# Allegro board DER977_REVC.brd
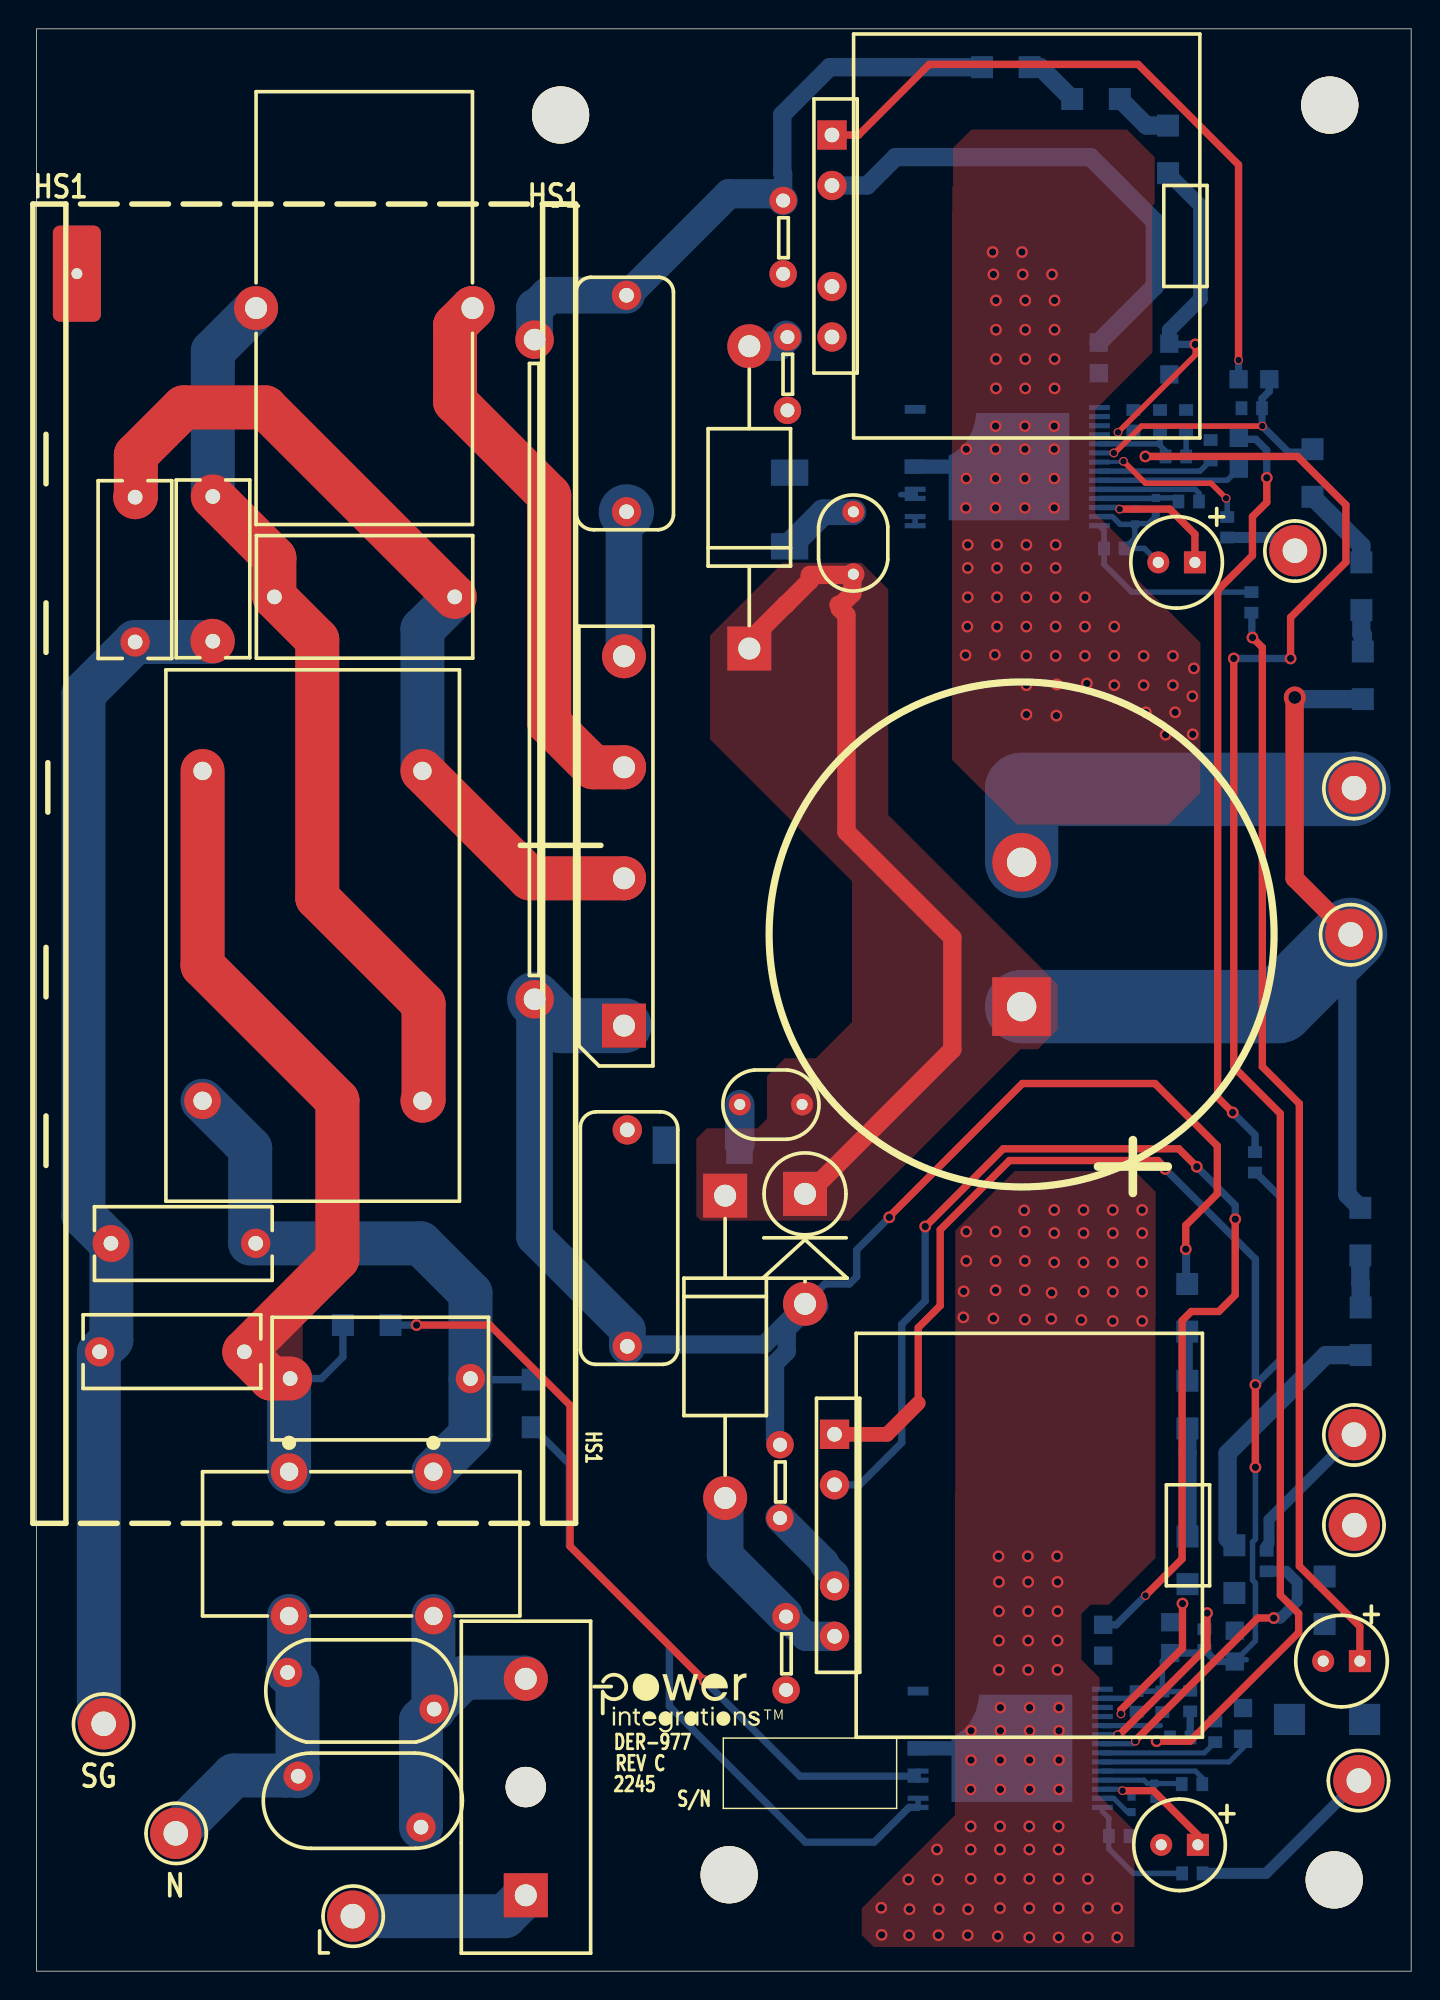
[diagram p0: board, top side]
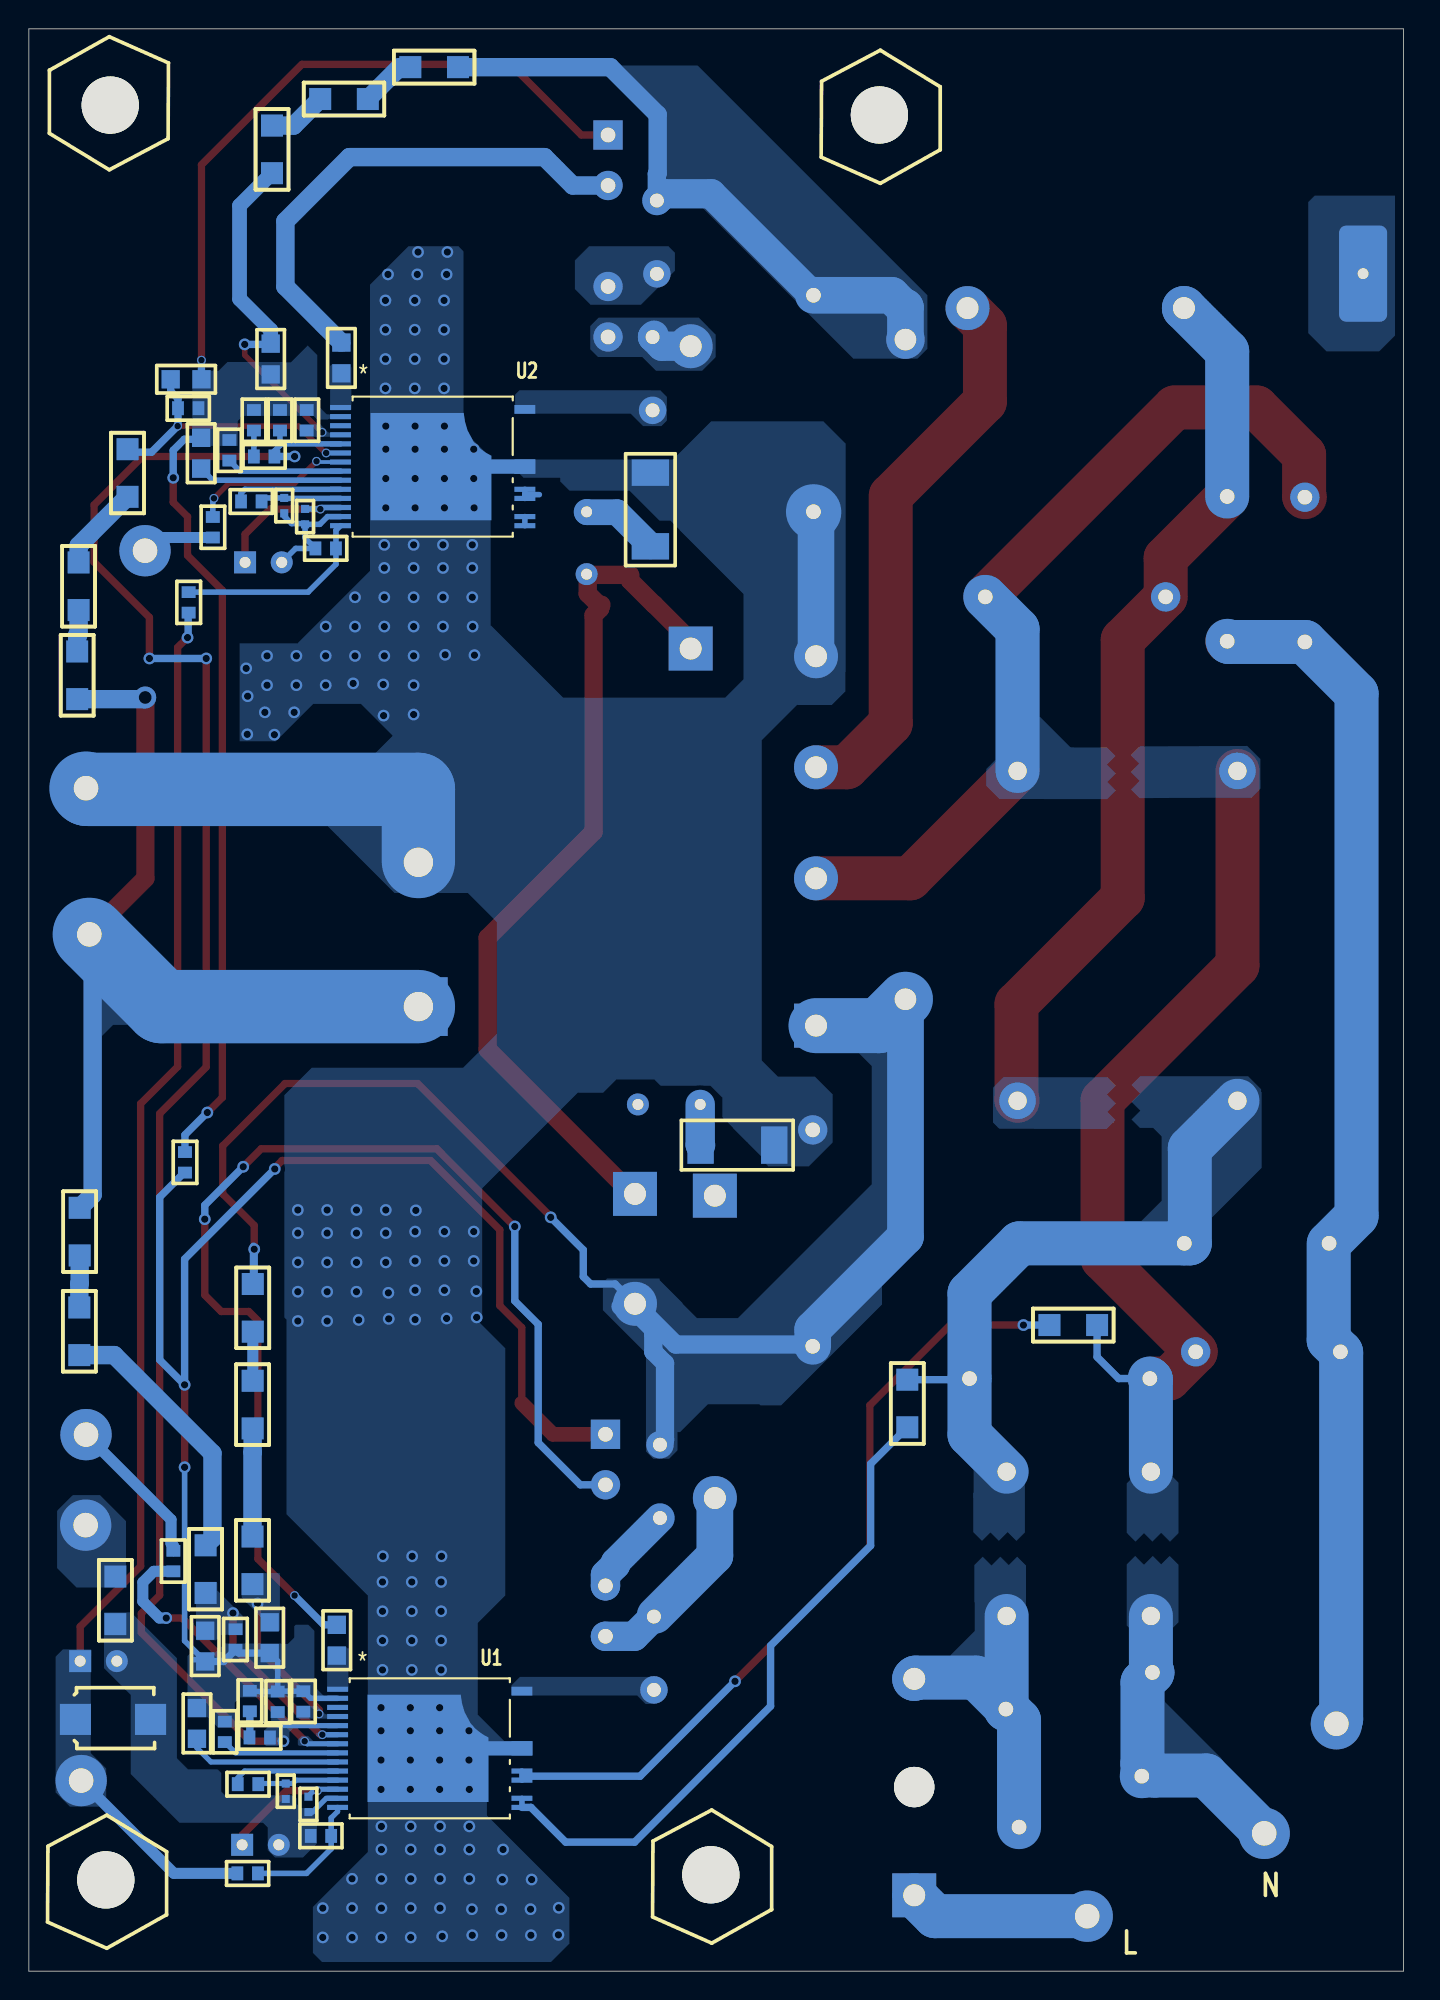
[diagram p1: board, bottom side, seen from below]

Outline 95.28 x 134.62 mm; copper layers: TOP, BOTTOM. Coordinates in mm from the lower left corner of the outline.
Outline path: 0,134.62 95.28,134.62 95.28,0 0,0 0,134.62

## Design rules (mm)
constraint set DEFAULT: min track width 0.508

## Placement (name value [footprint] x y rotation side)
BR1  GBJ1006-BP  [PI_DAX_BRIDG_GBJ]  40.72 65.53 90 top
C1  1 nF  [PI_NP475X200LS395D040]  14.4 42.93 180 top
C2  1 nF  [PI_NP475X200LS395D040]  5.16 50.44 0 top
C3  330 nF  [PINP_XCAPRAD15X8P5X14HD040]  17.58 41.07 0 top
C4  330 nF  [PINP_XCAPRAD15X8P5X14HD040]  16.48 95.25 0 top
C5  1 nF  [PI_NP475X200LS395D040]  6.83 102.16 270 top
C6  1 nF  [PI_NP475X200LS395D040]  12.22 92.18 90 top
C7  680 nF  [PINPCAPRAD17P5X6P7LS15]  40.89 116.15 270 top
C9  47 uF  [PIPOLCAPCYLD250LS100030]  91.72 21.49 180 top
C10  470 pF  [PISMC0603]  76.25 17.98 90 bottom
C11  1 uF  [PISMC0603]  74.32 9.37 0 bottom
C12  100 uF-NP  [PIPOLCAPCYLD250LS100030]  80.49 8.76 180 top
C13  2.2 uF  [PISMC0402]  75.9 12.09 270 bottom
C14  2.2 uF  [PISMC0402]  77.47 13 270 bottom
C15  100 nF  [PISMC0603]  78.03 17.96 90 bottom
C16  1 uF  [PISMC0603]  79.96 18.01 90 bottom
C17  470 pF  [PISMC0603]  80.95 23.7 270 bottom
C18  10 nF  [PI_NP_CAP250X200LS170D030]  53.06 60.07 180 top
C20  10 nF  [PI_NP_CAP250X200LS170D030]  56.62 96.82 90 top
C22  470 pF  [PISMC0603]  76.02 106.78 90 bottom
C23  1 uF  [PISMC0603]  73.99 98.61 0 bottom
C25  2.2 uF  [PISMC0402]  76.13 101.35 270 bottom
C26  100 uF  [PIPOLCAPCYLD250LS100030]  80.29 97.64 180 top
C27  2.2 uF  [PISMC0402]  77.58 102.11 270 bottom
C28  470 pF  [PISMC0603]  84.94 108.33 180 bottom
C29  100 nF  [PISMC0603]  77.87 106.78 90 bottom
C30  1 uF  [PISMC0603]  79.67 106.78 90 bottom
C31  680 nF  [PINPCAPRAD17P5X6P7LS15]  40.94 43.31 90 top
C32  470 uF  [PIPOLCAPCLYD35MMLS10]  68.28 66.85 90 top
C33  2.2 nF  [PINPYCAPRAD540X290LS400040]  17.4 20.7 0 top
D1  S1AB-13-F  [PISMSMB]  92.05 17.45 180 bottom
D2  1N5408G  [PIDV300X200X060DO15D0201AD]  53.26 53.87 270 top
D3  MUR460  [PIDV300X200X060DO15D0201AD#2]  47.73 53.75 270 top
D4  MUR460  [PIDV300X200X060DO15D0201AD#2]  49.4 91.67 90 top
FH1  Fuse Holder  [PI_FUSEHOLDER_5X20MM]  33.91 5.26 0 top
HS1  BRIDGE HEATSINK, SHTM, DER-977,  PI CUST, AL 3003  [PI_HS_1P_DER977]  2.03 31.04 0 top
JP1  J  [PI_JUMPER200]  51.53 36.49 270 top
JP2  J  [PI_JUMPER200]  51.95 24.57 270 top
JP3  J  [PI_JUMPER200]  51.75 122.72 270 top
JP4  J  [PI_JUMPER200]  52.04 113.26 270 top
JP5  J  [PI_JUMPER1800-18AWG-SLD]  34.52 67.36 90 top
L1  1.1 mH  [PIIND4P22X10LS10MM050]  22.5 29.62 270 top
L3  220 uH  [PI2P30X15X15LSD60]  15.21 115.27 0 top
L4  5 mH  [PIIND4P1450X800LS900X600050]  26.75 60.33 180 top
NOREF  -  []  2.41 119.53 0 top
NOREF#2  -  []  -147.56 133.08 0 top
NOREF#3  -  []  0 134.62 0 top
NOREF#4  -  []  95.28 0 90 top
NOREF#5  -  []  -232.28 -146.71 0 top
NOREF#6  -  []  38.53 21.11 0 top
NOREF#7  -  []  2.79 115.77 90 top
POST-CRKT_BRD_6-32_HEX1  Post Hex, 6-32, snap, 0.375L, NYL  [PIMTGHOLED156]  36.32 128.65 270 bottom
POST-CRKT_BRD_6-32_HEX2  Post Hex, 6-32, snap, 0.375L, NYL  [PIMTGHOLED156]  89.64 129.34 90 bottom
POST-CRKT_BRD_6-32_HEX3  Post Hex, 6-32, snap, 0.375L, NYL  [PIMTGHOLED156]  89.94 6.32 270 bottom
POST-CRKT_BRD_6-32_HEX4  Post Hex, 6-32, snap, 0.375L, NYL  [PIMTGHOLED156]  48.01 6.68 270 bottom
R4  1  [PISMR1206]  89.28 27.36 270 bottom
R5  6.2 M  [PISMR1206]  79.76 44.32 90 bottom
R6  6.2 M  [PISMR1206]  79.76 37.62 90 bottom
R7  3.74 M  [PISMR1206]  79.77 30.12 270 bottom
R8  165 k  [PISMR0805]  78.58 24.18 270 bottom
R9  0.0  [PISMR0603]  80.8 12.96 180 bottom
R10  10 k  [PISMR0805]  73.93 24 270 bottom
R11  20 k  [PISMR0603]  85.26 29.13 270 bottom
R12  332 k  [PISMR0603]  81.69 15.88 90 bottom
R13  DNP  [PISMR0805]  83.62 16.1 90 bottom
R14  39 k  [PISMR0603]  78.56 16.2 0 bottom
R15  0.0  [PISMR0603]  80.82 6.78 180 bottom
R16  6.2 M  [PISMR1206]  91.75 49.61 90 bottom
R17  6.2 M  [PISMR1206]  91.78 42.7 90 bottom
R18  3.74 M  [PISMR1206]  83.03 29.51 270 bottom
R19  158 k  [PISMR0805]  83.05 23.6 270 bottom
R20  75 k  [PISMR1206]  21.23 44.78 0 bottom
R21  75 k  [PISMR1206]  34.39 37.69 90 bottom
R22  6.2 M  [PISMR1206]  68.83 131.97 180 bottom
R23  6.2 M  [PISMR1206]  75.08 129.76 180 bottom
R24  0.0  [PISMR0603]  80.57 101.87 180 bottom
R25  10 k  [PISMR0805]  73.61 112.88 270 bottom
R26  6.2 M  [PISMR1206]  91.93 91.47 270 bottom
R27  20 k  [PISMR0603]  82.52 99.36 90 bottom
R28  3.74 M  [PISMR1206]  78.42 127.92 270 bottom
R29  6.2 M  [PISMR1206]  91.83 97.64 270 bottom
R30  3.74 M  [PISMR1206]  88.44 102.18 90 bottom
R31  165 k  [PISMR0805]  78.51 112.8 270 bottom
R33  DNP  [PISMR0805]  83.33 104.14 90 bottom
R34  39 k  [PISMR0603]  78.26 104.98 0 bottom
R35  332 k  [PISMR0603]  81.38 104.7 90 bottom
R36  158 k  [PISMR0805]  85.45 110.33 180 bottom
R37  0.0  [PISMR0603]  84.2 94.16 90 bottom
R38  0  [PISMR0603]  84.45 55.35 90 bottom
R39  0.47  [PISMR2010]  48.72 57.25 180 bottom
R40  0.47  [PISMR2010]  52.2 98.76 90 bottom
RV1  320 Vac  [PIDISC500X225LS335X140040]  18.14 13.51 0 top
T1  ATQ28/18  [PI_BOBBIN_ATQ28_V_4P]  68.81 30.21 0 top
T4  ATQ28/18  [PI_BOBBIN_ATQ28_V_4P]  68.63 120.26 0 top
TP1  RED  [PITPKEYSTONE125X125]  21.92 3.81 90 top
TP2  CON1  [PITPKEYSTONE125X125]  9.65 9.55 90 top
TP3  GRN  [PITPKEYSTONE125X125]  4.65 17.14 0 top
TP4  CON1  [PITPKEYSTONE125X125]  91.65 13.21 270 top
TP5  CON1  [PITPKEYSTONE125X125]  91.34 30.91 270 top
TP6  CON1  [PITPKEYSTONE125X125]  91.08 71.86 0 top
TP7  CON1  [PITPKEYSTONE125X125]  91.31 81.99 0 top
TP8  CON1  [PITPKEYSTONE125X125]  91.31 37.19 0 top
TP9  CON1  [PITPKEYSTONE125X125]  87.22 98.45 0 top
U1  PFGCZ  [INSOP-T28F]  67.49 15.44 180 bottom
U2  PFGCZ  [INSOP-T28F]  67.28 104.28 180 bottom

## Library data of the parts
BR1 = DIODE BRIDGE_1234
C1 C2 C5 C6 = CAP NP: tolerance: 20; room: 1
C3 C4 = CAP NP: alternate symbols: (pinp_xcaprad15x8p5x14Hd040H); room: 1
C7 C31 = CAP NP: room: 1
C9 C12 C26 = CAP POL: alternate symbols: (pipolcapcyld250ls100030h); tolerance: 20; room: 2
C10 C11 C15-C18 C20 C22 C23 C28-C30 = CAP NP: room: 2
C13 C14 C25 C27 = CAP NP: alternate symbols: (pismr0402_1); room: 2
C32 = CAP POL: alternate symbols: (pipolcapclyd35mmls10H)
C33 = CAP NP: alternate symbols: (pinpycaprad540x290ls400040h)
D1 = DIODE: room: 2
D2 = DIODE: alternate symbols: (pidv300x472x060do14wbead,pidax800x225060do15do201ad,pidv300x200x060do14wbead); room: 2
D3 D4 = DIODE: alternate symbols: (pidax800x225060do15do201ad,pidv300x200x060do14wbead); room: 2
FH1 = FUSEHOLDER
HS1 = hs_1P_DER977
JP1-JP4 = JUMPER_1: room: 2
JP5 = JUMPER_1
L1 = CMC_ 4P_12_43
L3 = INDUCTOR: room: 1
L4 = INDUCTOR_4P_revD
POST-CRKT_BRD_6-32_HEX1-POST-CRKT_BRD_6-32_HEX4 = POST_CRKT_BRD_6-32_HEX
R4-R14 R16-R19 R22-R31 R33-R36 R39 R40 = R: room: 2
R15 R37 R38 = R
R20 R21 = R: room: 1
RV1 = VARISTOR: room: 1
T1 = Transformer_DER-977_PFSGAN_250W
T4 = BATQ28_4P/GENERIC: alternate symbols: (pi_bobbin_ATQ28_V_5P)
TP1 TP2 = TESTPOINT: room: 1
TP3 = TESTPOINT
TP4-TP9 = TESTPOINT: room: 2
U1 U2 = PFSGaN_InSOP-T28F28: User Part Number: PN; Tolerance: TOL; room: 2

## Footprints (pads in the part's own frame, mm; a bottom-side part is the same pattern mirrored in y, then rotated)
INSOP-T28F
  rect 1.448x0.356 smd: 1(-6.388,4.095) 2(-6.388,3.465) 3(-6.388,2.835) 4(-6.388,2.205) 5(-6.388,1.575) 6(-6.388,0.945) 7(-6.388,0.315) 8(-6.388,-0.315) 9(-6.388,-0.945) 10(-6.388,-1.575) 11(-6.388,-2.205) 12(-6.388,-2.835) 13(-6.388,-3.465) 14(-6.388,-4.095) 15(6.388,-4.095) 16(6.388,-3.465) 18(6.388,-2.205) 19(6.388,-1.575)
  rect 1.448x0.986 smd: 21(6.388,0)
  rect 1.448x0.61 smd: 28(6.388,3.967)
PI2P30X15X15LSD60
  round 3.048 hole 1.524: 1(0,0) 2(15,0)
PI_BOBBIN_ATQ28_V_4P
  rect 2.032x2.032 hole 1.016: 1(-13.5,7)
  round 2.032 hole 1.016: 2(-13.5,3.5) 3(-13.5,-3.5) 4(-13.5,-7)
PI_DAX_BRIDG_GBJ
  rect 3.048x3.048 hole 1.524: 1(0,0)
  round 3.048 hole 1.524: 2(10.211,0) 3(17.907,0) 4(25.603,0)
PI_FUSEHOLDER_5X20MM
  round 2.794 hole 2.794: (0,7.501)
  rect 3.048x3.048 hole 1.524: 1(0,0)
  round 3.048 hole 1.524: 2(0,15.001)
PI_HS_1P_DER977
  rrect 3.333x6.66 hole 0.75: 1(0.764,86.614)
PI_JUMPER200
  round 1.905 hole 0.965: 1(0,0) 2(5.08,0)
PI_JUMPER1800-18AWG-SLD
  round 2.667 hole 1.499: 1(0,0) 2(45.72,0)
PI_NP475X200LS395D040
  round 2.032 hole 1.016: 1(0,0) 2(10.033,0)
PI_NP_CAP250X200LS170D030
  round 1.524 hole 0.762: 1(0,0) 2(4.318,0)
PIDISC500X225LS335X140040
  round 2.032 hole 1.016: 1(0,0) 2(8.509,-3.531)
PIDV300X200X060DO15D0201AD
  rect 3.048x3.048 hole 1.524: 1(0,0)
  round 3.048 hole 1.524: 2(7.62,0)
PIDV300X200X060DO15D0201AD#2
  rect 3.048x3.048 hole 1.524: 1(0,0)
  round 3.048 hole 1.524: 2(20.955,0)
PIIND4P22X10LS10MM050
  round 2.54 hole 1.27: 1(-5,5) 2(5,5) 3(5,-5) 4(-5,-5)
PIIND4P1450X800LS900X600050
  round 2.54 hole 1.27: 1(0,0) 2(15.24,0) 3(15.24,-22.86) 4(0,-22.86)
PIMTGHOLED156
  round 3.962 hole 3.962: 1(0,0)
PINP_XCAPRAD15X8P5X14HD040
  round 2.032 hole 1.016: 1(0,0) 2(12.499,0)
PINPCAPRAD17P5X6P7LS15
  round 2.032 hole 1.016: 1(0,0) 2(15.001,0)
PINPYCAPRAD540X290LS400040
  round 2.032 hole 1.016: 1(0,0) 2(10.16,-2.54)
PIPOLCAPCLYD35MMLS10
  rect 4.064x4.064 hole 2.032: 1(0,0)
  round 4.064 hole 2.032: 2(10,0)
PIPOLCAPCYLD250LS100030
  rect 1.524x1.524 hole 0.762: 1(0,0)
  round 1.524 hole 0.762: 2(2.54,0)
PISMC0402
  rect 0.559x0.559 smd: 1(0,0) 2(1.067,0)
PISMC0603
  rect 0.813x0.965 smd: 1(0,0) 2(1.422,0)
PISMR0603
  rect 0.813x0.965 smd: 1(0,0) 2(1.422,0)
PISMR0805
  rect 1.27x1.27 smd: 1(0,0) 2(2.134,0)
PISMR1206
  rect 1.524x1.524 smd: 1(0,0) 2(3.302,0)
PISMR2010
  rect 1.829x2.591 smd: 1(0,0) 2(5.105,0)
PISMSMB
  rect 2.159x2.159 smd: 1(0,0) 2(5.207,0)
PITPKEYSTONE125X125
  round 3.556 hole 1.702: 1(0,0)

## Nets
GND_EARTH: C1.2 C2.1 C5.2 C6.1 TP3.1
VBUS: C18.1 C20.1 C32.1 D2.1 D3.1 D4.1 R16.2 R26.2 TP6.1
VCC: C9.1 D1.1 R15.1 R37.1 TP4.1
CPIN: C15.1 C29.1 R14.1 R34.1 U1.5 U2.5
D1-1: R21.1 U1.15 U1.16
D2-1: R20.2 U1.18 U1.19
G1: C22.2 C28.2 C29.2 C30.2 R31.2 R33.2 R35.2 R36.2 R38.2 T4.1 U2.2
PG_1: R11.1 TP8.1
PG_2: R27.1 TP9.1
RTN: BR1.4 C7.2 C31.2 C32.2 R39.2 R40.2 TP7.1 U1.21 U2.21
VRECT: BR1.1 C31.1 D2.2 JP1.1 JP5.1 R5.2
N2269146: FH1.1 TP1.1
N2269222: C1.1 C3.1 L1.4 L4.3 R20.1
N2269270: BR1.2 C4.2 C5.1 L4.4
N2269580: C4.1 C6.2 L3.1 L4.1
N2273543: C10.1 R7.2 R8.1 U1.4
N2273803: R4.1 TP5.1
N2273811: C9.2 C11.2 C12.2 C13.2 C14.2 D1.2 R4.2 U1.13
N2277982: R5.1 R6.2
N2280643: C10.2 C15.2 C16.2 C17.2 R8.2 R12.2 R13.2 R19.2 R38.1 T1.1 U1.2
N2280913: R13.1 U1.9
N2282320: C12.1 C13.1 U1.12
N2282978: C14.1 R9.2 U1.11
N2283364: R12.1 U1.8
N2283809: R10.2 U1.1
N2285705: C11.1 R15.2 U1.14
N2292996: C17.1 R18.2 R19.1 U1.6
N12253154: R16.1 R17.2
N12253176: R17.1 R18.1
N12296335: R11.2 U1.7
N12310541: R9.1 U1.10
N12311649: C33.1 L1.3 RV1.1 TP2.1
N12311801: C33.2 FH1.2 L1.2 RV1.2
N12332974: JP1.2 T1.3
N12355245: JP2.2 U1.28
N12357298: BR1.3(AC2) L3.2
N12358168: C2.2 C3.2 L1.1 L4.2 R21.2
N12370171: C7.1 JP3.1 JP5.2 R22.2
N12370179: JP3.2 T4.3
N12370191: R25.1 T4.2
N12370241: R22.1 R23.2
N12370315: R24.1 U2.10
N12370431: C27.1 R24.2 U2.11
N12370475: U2.15 U2.16
N12370487: U2.18 U2.19
N12370503: JP4.2 U2.28
N12370525: R25.2 U2.1
N12370581: R26.1 R29.2
N12370631: R27.2 U2.7
N12370663: C22.1 R28.2 R31.1 U2.4
N12370753: C23.1 R37.2 U2.14
N12370795: R29.1 R30.1
N12370825: C25.1 C26.1 U2.12
N12370935: C23.2 C25.2 C26.2 C27.2 U2.13
N12371013: R35.1 U2.8
N12371017: R33.1 U2.9
N12371025: C28.1 R30.2 R36.1 U2.6
N12389668: R6.1 R7.1
N12393657: R10.1 T1.2
N12394061: D3.2 JP2.1 T1.4
N12395901: R23.1 R28.1
N12410952: D4.2 JP4.1 T4.4
N12423276: C16.1 R14.2
N12448428: C18.2 R39.1
N12448931: C20.2 R40.1
N123711831: C30.1 R34.2

Pads without a net: HS1 1; POST-CRKT_BRD_6-32_HEX1 1; POST-CRKT_BRD_6-32_HEX2 1; POST-CRKT_BRD_6-32_HEX3 1; POST-CRKT_BRD_6-32_HEX4 1; U1 3; U2 3

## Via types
v1: diameter 0.813, hole 0.508, TOP to BOTTOM, 191 vias
v2: diameter 0.61, hole 0.457, TOP to BOTTOM, 12 vias
v3: diameter 1.524, hole 0.889, TOP to BOTTOM, 3 vias

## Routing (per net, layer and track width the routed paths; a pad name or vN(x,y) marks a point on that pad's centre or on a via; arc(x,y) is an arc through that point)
GND_EARTH: length 83.2
  TOP w2.54: v3(5.18,50.42) C2.1
  TOP w3.048: v3(12.19,92.2) C6.1
  BOTTOM w3.048: v3(12.19,92.2) 12.12,92.13 C5.2 3.25,88.54 3.25,52.35 C2.1 ; v3(5.18,50.42) 5.18,43.74 C1.2 4.32,42.88 4.32,17.48 TP3.1
VBUS: length 127.7
  TOP w1.27: TP6.1 87.2,75.74 87.2,87.99 87.21,88 v3(87.21,88.28) ; 55.68,94.61 55.68,94.44 56.13,93.98 56.13,78.97 63.47,71.63 63.47,63.88 53.11,53.52 ; 55.68,94.61 55.59,94.7 ; 55.68,94.61 56.54,95.48 56.54,96.65 ; 53.59,96.7 53.59,96.37 51.97,94.74 51.94,94.74 49.4,92.2 D4.1 ; 53.59,96.77 56.59,96.77
  BOTTOM w1.27: 90.85,71.63 90.85,53.81 R16.2 ; v3(87.21,88.28) 87.33,88.16 R26.2
  BOTTOM w5.08: C32.1 86.08,66.85 TP6.1
VCC: length 89.3
  TOP w0.508: C9.1 91.72,23.88 87.53,28.07 87.53,60.12 84.96,62.69 84.96,91.74 v1(84.28,92.43)
  BOTTOM w0.508: v1(84.28,92.43) 84.23,92.47 84.23,94.12 R37.1
  BOTTOM w0.762: R15.1 85.22,6.78 TP4.1
CPIN: length 125.4
  TOP w0.508: v1(86.92,90.98) 86.92,93.83 90.75,97.66 90.75,101.63 87.4,104.98 v1(76.86,104.98) ; v1(82.98,90.98) 82.98,62.66 86.21,59.44 86.21,26.06 87.48,24.79 87.48,23.47 79.95,15.94 v1(77.64,15.94)
  BOTTOM w0.356: 77.9,17.02 U1.5
  BOTTOM w0.381: R34.1 78.26,105.36 77.87,105.75 77.87,105.87 ; U2.5 77.86,105.85 77.87,105.87 ; 77.87,105.87 C29.1
  BOTTOM w0.508: v1(86.92,90.98) v1(82.98,90.98) ; R34.1 v1(76.86,104.98)
D1-1: length 46
  BOTTOM w0.381: U1.16 U1.15
  BOTTOM w0.508: U1.15 60.47,11.35 58.06,8.94 53.29,8.94 43.87,18.36 43.87,22.56 36.93,29.49 36.93,35.15 R21.1
D2-1: length 56
  TOP w0.508: v1(46.33,20.09) 36.98,29.44 36.98,39.22 31.42,44.78 v1(26.34,44.78)
  BOTTOM w0.254: 60.74,13.51 U1.19
  BOTTOM w0.381: U1.19 U1.18
  BOTTOM w0.508: 60.74,13.51 52.91,13.51 v1(46.33,20.09) ; R20.2 v1(26.34,44.78)
G1: length 101.4
  TOP w0.508: v2(83.31,111.66) 83.31,125.2 76.35,132.16 61.87,132.16 56.98,127.26 T4.1 ; v1(85.27,103.5) 85.27,101.8 84.28,100.81 84.28,98.12 81.86,95.71 81.86,60.55 v1(82.91,59.51)
  BOTTOM w0.508: v1(85.27,103.5) 85.27,105.41 84.51,106.17 83.43,106.17 R33.2 ; v1(82.91,59.51) 84.45,57.96 84.45,56.77 ; R36.2 v2(83.31,111.66)
PG_1: length 10.6
  BOTTOM w0.762: R11.1 85.26,29.48 85.42,29.64 85.42,31.29 TP8.1
PG_2: length 5.1
  BOTTOM w0.762: R27.1 86.31,99.36 TP9.1
RTN: length 38.2
  BOTTOM w2.54: 40.87,101.13 40.72,100.98 BR1.4
  BOTTOM w3.81: 40.87,101.13 C7.2
  BOTTOM w5.08: TP7.1 91.23,81.91 68.28,81.91 68.28,76.91
  vias: v1(58.55,4.39) v1(58.57,2.51) v1(60.43,6.35) v1(60.5,4.29) v1(60.48,2.49) v1(62.41,8.43) v1(62.46,6.35) v1(62.53,4.29) v1(62.51,2.49) v1(64.24,45.31) v1(64.26,47.12) v1(64.44,105.49) v1(64.44,103.45) v1(64.41,101.42) v1(64.39,91.21) v1(64.44,51.26) v1(64.44,49.23) v1(64.54,98.86) v1(64.54,97.26) v1(64.54,95.22) v1(64.52,93.19) v1(64.54,2.49) v1(64.57,4.29) v1(64.74,12.6) v1(64.74,10.03) v1(64.74,8.43) v1(64.74,6.4) v1(64.77,16.66) v1(64.77,14.63) v1(66.27,119.15) v1(66.32,117.6) v1(66.32,45.24) v1(66.42,91.24) v1(66.5,115.8) v1(66.5,113.77) v1(66.5,111.73) v1(66.5,109.7) v1(66.47,107.09) v1(66.47,105.49) v1(66.47,103.45) v1(66.47,101.42) v1(66.47,51.26) v1(66.47,49.23) v1(66.47,47.19) v1(66.57,98.86) v1(66.57,97.26) v1(66.57,95.22) v1(66.57,93.19) v1(66.62,2.41) v1(66.67,28.75) v1(66.7,26.97) v1(66.7,24.94) v1(66.7,22.91) v1(66.7,20.88) v1(66.8,18.26) v1(66.8,16.66) v1(66.8,14.63) v1(66.8,12.6) v1(66.78,10.03) v1(66.78,8.43) v1(66.78,6.4) v1(66.78,4.37) v1(68.3,119.15) v1(68.35,117.6) v1(68.53,115.8) v1(68.53,113.77) v1(68.53,111.73) v1(68.53,109.7) v1(68.5,107.09) v1(68.5,105.49) v1(68.5,103.45) v1(68.5,101.42) v1(68.45,52.73) v1(68.5,51.26) v1(68.5,49.23) v1(68.5,47.19) v1(68.5,45.16) v1(68.61,98.86) v1(68.61,97.26) v1(68.61,95.22) v1(68.61,93.19) v1(68.61,91.16) v1(68.61,89.13) v1(68.61,87.1) v1(68.71,28.75) v1(68.73,26.97) v1(68.73,24.94) v1(68.73,22.91) v1(68.73,20.88) v1(68.83,18.26) v1(68.83,16.66) v1(68.83,14.63) v1(68.83,12.6) v1(68.81,10.03) v1(68.81,8.43) v1(68.81,6.4) v1(68.81,4.37) v1(68.81,2.34) v1(70.33,45.21) v1(70.38,117.6) v1(70.36,47.02) v1(70.54,107.09) v1(70.54,105.49) v1(70.54,103.45) v1(70.54,101.42) v1(70.54,52.76) v1(70.54,51.16) v1(70.54,49.12) v1(70.56,115.8) v1(70.56,113.77) v1(70.56,111.73) v1(70.56,109.7) v1(70.64,98.86) v1(70.64,97.26) v1(70.64,95.22) v1(70.64,93.19) v1(70.64,91.16) v1(70.71,89.18) v1(70.69,87.02) v1(70.74,28.75) v1(70.76,26.97) v1(70.76,24.94) v1(70.76,22.91) v1(70.76,20.88) v1(70.84,10.03) v1(70.84,8.43) v1(70.84,6.4) v1(70.84,4.37) v1(70.84,2.34) v1(70.87,18.26) v1(70.87,16.66) v1(70.87,14.63) v1(70.87,12.6) v1(72.42,45.14) v1(72.57,52.76) v1(72.57,51.16) v1(72.57,49.12) v1(72.57,47.09) v1(72.67,95.22) v1(72.67,93.19) v1(72.67,91.16) v1(72.8,89.26) v1(72.87,6.4) v1(72.87,4.37) v1(72.87,2.34) v1(74.6,52.76) v1(74.6,51.16) v1(74.6,49.12) v1(74.6,47.09) v1(74.6,45.06) v1(74.7,93.19) v1(74.7,91.16) v1(74.7,89.13) v1(74.9,4.37) v1(74.9,2.34) v1(76.63,52.76) v1(76.63,51.16) v1(76.63,49.12) v1(76.63,47.09) v1(76.63,45.06) v1(76.73,91.16) v1(76.73,89.13) v1(76.89,87.25) v1(78.26,85.7) v1(78.77,91.16) v1(78.77,89.13) v1(78.92,87.25) v1(80.11,88.37) v1(80.14,85.72) v1(80.21,90.3)
VRECT: length 110.1
  TOP w0.508: v1(59.11,52.25) 59.11,52.3 68.33,61.52 77.52,61.52 81.84,57.2 81.84,53.87 79.65,51.69 v1(79.65,50.04)
  BOTTOM w0.508: 79.71,50.24 79.71,47.68 ; 79.71,47.68 R5.2 ; 79.71,47.68 79.65,47.73 v1(79.65,50.04) ; v1(59.11,52.25) 56.85,49.99 56.85,48.13 56.34,47.62 54.64,47.62 D2.2
  BOTTOM w1.27: D2.2 53.26,45.75 51.82,44.31 51.99,44.14 51.99,42.94 51.18,42.12 51.18,36.84 JP1.1 ; D2.2 50.44,43.43 41.07,43.43 C31.1 ; D2.2 53.44,46.08 54.26,46.08
  BOTTOM w2.54: JP5.1 34.52,50.9 40.94,44.48 C31.1
  BOTTOM w3.81: BR1.1 36.35,65.53 JP5.1
N2269146: length 12.6
  BOTTOM w3.048: FH1.1 32.46,3.81 TP1.1
N2269222: length 63.7
  TOP w3.048: C3.1 16.26,41.07 C1.1 20.85,49.38 20.85,60.35 11.51,69.7 L4.3
  BOTTOM w0.508: R20.1 21.23,42.57 19.74,41.07 C3.1
  BOTTOM w3.048: C3.1 17.5,41 L1.4
N2269270: length 61.9
  TOP w3.048: C4.2 15.85,108.38 10.19,108.38 6.88,105.08 6.88,102.21 C5.1 ; BR1.2 34.19,75.74 L4.4
  BOTTOM w3.048: L4.4 26.75,93.01 C4.2
N2269580: length 62.3
  TOP w3.048: L4.1 26.82,60.4 26.82,67.03 19.46,74.4 19.46,92.28 C4.1 16.48,97.94 C6.2
  BOTTOM w3.048: L3.1 12.22,112.27 C6.2
N2273543: length 9.4
  TOP w0.508: v1(79.43,25.48) 79.43,22.38 75.16,18.11 v2(75.16,17.83)
N2273811: length 2.5
  BOTTOM w0.356: C13.2 75.62,11.02 74.66,11.98 U1.13
  BOTTOM w0.508: C12.2 77.95,8.84
N2277982: length 3.4
  BOTTOM w0.762: R5.1 79.76,40.93 R6.2
N2280643: length 105.6
  TOP w0.508: 61.11,39.37 61.11,44.6 62.64,46.13 62.64,51.38 67.44,56.18 77.72,56.18 78.23,55.68 v1(78.23,55.6) ; v1(84.48,40.64) v1(84.48,34.92)
  TOP w1.016: 61.11,39.37 58.95,37.21 T1.1
  BOTTOM w0.381: C15.2 78.03,21.5 R8.2 ; C15.2 79.91,19.38 C16.2 ; C15.2 78,19.41 C10.2 75.75,18.91 U1.2 ; 83.05,21.46 84.48,22.89 84.48,26.9 84.28,27.1 84.28,29.75 84.48,29.94 v1(84.48,34.92) ; 83.21,21.59 83.85,21.59
  BOTTOM w0.508: v1(78.23,55.6) 84.48,49.35 v1(84.48,40.64) 86.21,42.37 86.21,53.64 84.51,55.35 R38.1 ; R8.2 80.72,22.05 C17.2 81.76,21.46 83.05,21.46
  BOTTOM w0.762: 55.32,37.22 T1.1
N2280913: length 10.8
  BOTTOM w0.356: R13.1 83.62,15.47 82.65,14.5 U1.9
N2282320: length 9.4
  TOP w0.508: C12.1 80.49,9.43 77.41,12.51 v2(75.28,12.51)
  BOTTOM w0.356: C13.1 75.9,12.15 75.54,12.51 v2(75.28,12.51) 75.17,12.61 U1.12
N2282978: length 5.6
  BOTTOM w0.356: U1.11 76.76,13.24 76.99,13 C14.1 79.33,13 R9.2
N2283364: length 8.1
  BOTTOM w0.356: U1.8 80.95,15.13 R12.1
N2285705: length 8.8
  BOTTOM w0.356: U1.14 73.88,11.06 74.32,10.62
  BOTTOM w0.381: R15.2 76.03,6.78 74.32,8.48 C11.1 74.32,10.62
N2292996: length 12.2
  TOP w0.508: 81.05,24.89 v1(81.13,24.82) 81.13,22.45 75.06,16.39 v2(74.94,16.39)
  BOTTOM w0.356: U1.6 v2(74.94,16.39)
N12253154: length 3.6
  BOTTOM w1.27: R17.2 91.78,47.65 91.75,47.68 R16.1
N12253176: length 18.6
  BOTTOM w1.27: R17.1 89.36,42.7 82.55,35.89 82.55,29.99 R18.1
N12296335: length 21.4
  TOP w0.508: v2(76.16,15.94) 76.16,15.99 84.65,24.47 v1(85.75,24.47)
  BOTTOM w0.356: v2(76.16,15.94) 75.98,15.76 U1.7
  BOTTOM w0.762: v1(85.75,24.47) 86.23,24.47 87.38,25.62 87.38,26.95 86.61,27.71 R11.2
N12310541: length 7.6
  BOTTOM w0.356: U1.10 80.33,13.87 80.8,13.4 R9.1
N12311649: length 22.7
  BOTTOM w3.048: 17.24,13.56 18.08,13.56 ; 17.24,13.56 13.67,13.56 TP2.1 ; 17.24,13.56 18.08,14.4 ; 18.08,13.56 18.08,14.4 ; 18.08,13.56 RV1.1 ; L1.3 17.5,20.81 C33.1 18.08,20.02 18.08,14.4
N12311801: length 22.5
  BOTTOM w3.048: 27.56,18.29 C33.2 27.5,18.22 L1.2 ; 27.56,18.29 29.62,20.35 33.82,20.35 FH1.2 ; 27.56,18.29 26.64,17.37 RV1.2
N12332974: length 6.3
  BOTTOM w2.032: JP1.2 54.61,28.33 54.61,28.17 55.31,27.47 T1.3
N12357298: length 38.4
  TOP w3.048: BR1.3 38.58,83.44 35.53,86.49 35.53,102.26 29.01,108.79 29.01,114.06 L3.2
N12358168: length 45.7
  BOTTOM w0.508: C3.2 30.15,41 R21.2
  BOTTOM w3.048: L4.2 14.81,57.02 14.81,50.44 C2.2 26.62,50.44 30.08,46.99 C3.2 30.08,37.19 L1.1
N12370171: length 45.8
  BOTTOM w0.762: 51.69,122.78 51.69,124.62
  BOTTOM w1.27: R22.2 54.98,131.97 51.69,128.68 51.69,124.62 51.75,124.56 JP3.1
  BOTTOM w2.032: JP3.1 51.28,123.19 47.98,123.19 41.05,116.26
  BOTTOM w2.54: JP5.2 34.52,115.32 34.54,115.34 34.67,115.34 35.48,116.15 C7.1
N12370191: length 35
  BOTTOM w1.27: T4.2 57.57,123.76 59.54,125.73 73.05,125.73 77.5,121.28 77.5,116.76 R25.1
N12370241: length 3.9
  BOTTOM w1.27: R23.2 69.57,131.97 R22.1
N12370315: length 7.6
  BOTTOM w0.381: R24.1 80.57,101.87 80.57,102.43 80.3,102.7 U2.10
N12370431: length 5.6
  BOTTOM w0.381: U2.11 77.54,102.08 C27.1 78.91,102.11 R24.2
N12370475: length 0.6
  BOTTOM w0.381: U2.16 U2.15
N12370487: length 1.6
  BOTTOM w0.381: U2.19 60.9,102.34 ; 60.9,102.34 59.89,102.34 ; 60.9,102.34 U2.18
N12370581: length 2.9
  BOTTOM w1.27: R29.2 91.83,92.68 91.93,92.58 R26.1
N12370631: length 11.2
  TOP w0.381: v2(82.45,102.08) 81.41,103.12 76.86,103.12 v2(75.34,104.65)
  BOTTOM w0.254: U2.7 75.28,104.59 v2(75.34,104.65)
  BOTTOM w0.381: R27.2 82.52,102.01 v2(82.45,102.08)
N12370663: length 24.1
  TOP w0.381: v1(80.31,112.75) 80.31,112.01 v2(74.96,106.65)
  BOTTOM w0.254: 75.01,106.68 74.98,106.68 v2(74.96,106.65)
  BOTTOM w0.381: 78.74,113.03 78.63,113.03 78.51,112.91
  BOTTOM w0.508: v1(80.31,112.75) 78.56,112.75 R31.1
  BOTTOM w1.016: R31.1 78.51,113.74 80.67,115.9 80.67,122.37 R28.2
N12370753: length 13.8
  BOTTOM w0.381: R37.2 75.92,95.58 73.99,97.51 C23.1 73.99,99.87 U2.14
N12370795: length 6
  BOTTOM w1.27: R30.1 91.83,98.8 R29.1
N12370825: length 10.5
  TOP w0.508: 80.29,97.58 C26.1 80.29,99.59 78.55,101.33 v2(75.07,101.33)
  BOTTOM w0.381: C25.1 75.09,101.35 v2(75.07,101.33) 74.96,101.45 U2.12
N12370935: length 9.3
  BOTTOM w0.381: C26.2 76.78,98.61 C23.2 76.13,99.32 C25.2 ; C25.2 76.18,100.33 77.06,100.33 77.58,100.84 C27.2 ; C25.2 75.11,100.28 74.57,100.82 U2.13
N12371013: length 8
  BOTTOM w0.381: U2.8 80.64,103.96 R35.1
N12371017: length 10
  BOTTOM w0.381: U2.9 82.53,103.33 R33.1
N12371025: length 19.8
  TOP w0.381: v2(84.96,107.09) 76.58,107.09 74.72,105.22 v2(74.67,105.22)
  BOTTOM w0.254: U2.6 v2(74.67,105.22)
  BOTTOM w0.508: R30.2 88.23,105.28 86.77,105.28 v2(84.96,107.09) 84.94,107.11 C28.1 84.94,108.99 85.45,109.5 R36.1
N12389668: length 7.5
  BOTTOM w1.27: R6.1 79.76,35.97 79.77,35.96 R7.1
N12393657: length 81.4
  TOP w0.508: v1(61.59,51.61) 61.62,51.61 67.01,57 79.17,57 v1(80.42,55.75) ; v1(83.08,52.12) 83.08,46.86 81.94,45.72 80.04,45.72 79.4,45.09 79.4,28.57 v2(76.86,26.04)
  BOTTOM w0.508: v2(76.86,26.04) 74.83,24 R10.1 ; v1(61.59,51.61) 61.59,46.46 59.97,44.83 59.97,36.63 57.05,33.71 T1.2 ; v1(80.42,55.75) 83.08,53.09 v1(83.08,52.12)
N12394061: length 13.9
  BOTTOM w2.032: 51.86,24.67 JP2.1 53.32,23.21 T1.4
  BOTTOM w2.54: 51.86,24.67 47.73,28.8 D3.2
N12395901: length 4.1
  BOTTOM w1.27: R28.1 76.92,127.92 R23.1
N12410952: length 3.1
  BOTTOM w2.032: D4.2 51.41,112.62 JP4.1 52.02,113.28 ; 52.04,113.28 51.94,113.39
N12423276: length 1.8
  BOTTOM w0.508: R14.2 79.96,16.22 C16.1
N12448428: length 2.8
  BOTTOM w2.032: R39.1 48.74,57.28 C18.2
N12448931: length 5.4
  BOTTOM w1.778: C20.2 56.59,101.12 54.51,101.12 52.2,98.81 R40.1
N123711831: length 1.8
  BOTTOM w0.381: C30.1 79.68,106.78 R34.2

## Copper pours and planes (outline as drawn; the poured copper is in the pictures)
VBUS on TOP: 46.05,52.02 45.72,52.35 45.72,57.68 46.46,58.42 49.96,58.42 50.62,59.08 50.62,62.03 51.87,63.27 54,63.27 56.53,65.8 56.53,75.53 46.69,85.37 46.69,92.58 51.71,97.61 57.2,97.61 59.03,95.78 59.03,80.14 70.76,68.4 70.76,65.25 69.41,63.89 68.21,63.89 56.34,52.02
VBUS on BOTTOM: 90.47,64.34 90.47,64.54 89.43,65.58 87.63,65.58 87.63,66.29 90.22,68.88 90.7,68.4 90.7,64.57
VCC on BOTTOM: 93.42,12.4 92.43,11.4 89.94,11.4 89.92,11.43 89.92,14.05 90.98,15.11 90.98,21.82 90.96,21.84 90.96,22.3 92.91,22.3 93.42,21.79
CPIN on BOTTOM: 78.49,18.36 78.49,17.14 78.97,16.66 78.97,15.75 78.74,15.52 77.57,15.52 77.22,15.88 77.22,16.56 76.83,16.94 77.06,17.17 77.09,17.17 77.55,17.63 77.55,18.36
G1 on BOTTOM: 75.54,107.8 80.44,107.8 80.8,107.44 80.8,105.71 83.95,105.71 83.95,110.79 83.82,110.92 82.12,110.92 81.51,111.53 77.42,111.53 77.39,111.51 77.11,111.51 75.95,112.67 75.29,112.01 75.29,108.56 74.63,107.9 72.95,107.9 72.95,107.54 75.29,107.54
Net_74 on BOTTOM: 0.58,123.06 6.15,123.06 6.6,122.61 6.6,113.54 5.33,112.27 1.68,112.27 0.58,113.36
RTN on BOTTOM (solid shape): 71.6,100.56 63.22,100.56 63.22,103.79 60.17,103.79 60.17,104.77 63.22,104.77 63.22,105.03 63.6,105.24 63.88,105.45 64.16,105.68 64.47,106.03 64.87,106.79 65.05,107.4 65.14,108 71.6,108
RTN on BOTTOM (solid shape): 71.8,11.72 63.42,11.72 63.42,14.95 60.38,14.95 60.38,15.94 63.42,15.94 63.42,16.2 63.8,16.41 64.08,16.61 64.36,16.84 64.67,17.2 65.07,17.96 65.25,18.57 65.34,19.16 71.8,19.16
RTN on TOP: 77.34,122.35 77.34,112.19 73.38,108.23 73.38,101.07 75.9,98.55 75.9,96.85 80.67,92.08 80.67,81.69 78.44,79.45 67.97,79.45 63.45,83.97 63.45,121.97 63.47,122 63.47,123.7 63.56,123.79 63.53,123.83 63.53,126.36 64.8,127.64 75.59,127.64 77.5,125.73 77.5,122.5
RTN on TOP: 77.55,28.57 77.5,28.57 74.32,25.4 73.05,25.4 72.42,24.77 72.42,21.59 73.69,20.32 73.69,19.68 73.77,19.6 73.58,19.41 73.58,12.24 76.1,9.73 76.1,1.68 58.01,1.68 57.2,2.49 57.2,4.37 63.65,10.82 63.65,33.15 63.68,33.17 63.68,51.36 63.7,51.36 67.79,55.45 76.12,55.45 77.57,54 77.57,45.31 77.55,45.29
RTN on BOTTOM: 71.63,97.05 71.63,116.89 68.96,119.56 65.51,119.56 65.15,119.2 65.15,106.78 63.27,104.9 63.27,87.55 65.58,85.24 69.67,85.24 72.26,87.83 75.56,87.83 78.16,85.24 80.67,85.24 80.67,92.02 76.66,92.02
RTN on BOTTOM: outline of 90 points within 38.66,0.64 77.57,107.42
VRECT on BOTTOM: 52.5,36.02 51.99,35.51 50.9,35.51 50.32,36.09 50.32,37.36 50.14,37.36 48.21,39.29 44.65,39.29 44.58,39.22 43.13,39.22 36.14,46.2 36.14,47.47 33.91,49.71 33.91,61.09 36.8,63.98 37.11,63.98 36.86,63.73 36.86,54.53 46.13,45.26 48.97,45.26 49.96,46.25 49.96,46.3 51.56,47.9 51.56,48.04 51.59,48.01 55.19,48.01 55.32,47.88 55.37,47.88 55.49,47.76 55.49,45.81 52.5,42.82
VRECT on BOTTOM: 38.25,64.01 38.13,64.01 34.87,60.76 34.7,60.93 34.7,65.13 37.13,65.13
N2269222 on TOP: 18.44,45.01 18.44,41.78 18.49,41.73 16.51,41.73 15.27,42.98 17.3,45.01
N2269222 on BOTTOM: 19.18,30.38 18.57,29.77 17.98,30.35 17.4,29.77 16.79,30.38 16.18,29.77 15.6,30.35 15.6,33.86 16.89,35.15 17.83,35.15 19.18,33.81
N2269222 on BOTTOM: 18.11,84.89 18.29,84.89 18.9,84.27 18.31,83.69 18.89,83.11 18.28,82.5 18.89,81.89 18.3,81.3 10.53,81.34 9.91,81.96 9.92,84.02 10.82,84.92
N2269270 on BOTTOM: 22.66,84.4 26.44,84.4 26.85,84.81 26.85,86.33 25.86,87.33 25.58,87.33
N2269270 on BOTTOM: 23.37,81.24 20.55,81.23 19.94,81.84 20.52,82.42 19.94,83.01 20.55,83.62 19.93,84.22 20.52,84.81 23.54,84.82 25.37,84.82 25.39,84.82 27.33,84.83 27.4,84.83 28.92,83.31 28.92,82.15 28.02,81.25
N2269580 on BOTTOM: 23.37,58.38 20.55,58.37 19.94,58.98 20.52,59.56 19.94,60.15 20.55,60.76 19.93,61.36 20.52,61.95 23.54,61.96 25.37,61.96 25.39,61.96 27.71,61.97 27.8,61.87 27.81,61.87 28.45,61.24 28.45,58.82 28.02,58.39
N2273543 on BOTTOM: 79.2,24.56 79.2,23.57 77.93,23.57 77.88,23.62 77.88,27.56 77.9,27.58 80.52,27.58 80.52,25.88
N2273543 on BOTTOM: 73.15,17.83 74.73,17.83 75.29,18.39 76.73,18.39 76.73,17.58 76.63,17.48 73.18,17.48 73.15,17.5
N2273803 on BOTTOM: 88.54,26.59 91.97,26.59 93.32,27.94 93.32,31.9 92.23,32.99 90.35,32.99 88.54,31.19
N2273811 on BOTTOM: 75.44,11.3 76.43,11.3 76.71,11.58 76.71,11.96 76.94,12.19 81.69,12.19 81.94,12.45 81.94,13.74 82.18,13.98 84.24,13.98 85.01,14.76 85.01,21.69 88.19,24.87 90.04,24.87 90.07,24.84 90.07,21.01 88.21,19.15 88.21,13.67 84.84,10.29 79.04,10.29 78.71,9.96 78.71,8.38 78.21,7.87 76.28,7.87 75.31,8.84 75.31,11.18
N2280643 on BOTTOM: 75.74,18.97 80.64,18.97 81,18.62 81,16.89 82.17,16.89 82.88,17.6 84.28,17.6 84.28,21.84 84.02,22.1 82.32,22.1 81.71,22.71 77.62,22.71 77.6,22.68 77.32,22.68 76.89,23.11 76.89,23.9 76.78,24 75.9,24 75.49,23.6 75.49,19.74 74.83,19.08 73.15,19.08 73.15,18.72 75.49,18.72
N2283809 on BOTTOM: 74.6,19.38 74.6,22.43 74.5,22.53 73.33,22.53 73.13,22.33 73.13,19.41 73.15,19.38
N2292996 on BOTTOM: 80.44,23.27 80.44,24.61 82.22,26.39 82.22,26.9 82.27,26.95 83.69,26.95 83.69,22.99 83.64,22.94 82.3,22.94 81.92,23.32 80.49,23.32
N12296335 on BOTTOM: 73.15,15.95 75.56,15.95 75.92,16.31 76.35,16.31 76.63,16.03 76.63,15.7 76.56,15.62 73.2,15.62 73.18,15.6 73.15,15.62
N12311649 on BOTTOM: 15.6,28.17 16.21,28.78 16.79,28.19 17.37,28.78 17.98,28.17 18.59,28.78 19.18,28.19 19.18,23.95 19,23.77 16,23.77 15.6,24.18
N12311649 on BOTTOM: 12.62,14.38 12.62,14.76 17.5,19.63 18.21,18.92 18.21,13.11 13.89,13.11
N12311801 on BOTTOM: 29.72,25.76 29.72,23.57 31.72,21.56 31.6,21.44 28.12,21.44 28.12,24.16
N12311801 on BOTTOM: 26.16,28.12 26.77,28.73 27.36,28.14 27.94,28.73 28.55,28.12 29.16,28.73 29.74,28.14 29.74,25.58 28.57,24.41 26.39,24.41 26.16,24.64
N12355245 on BOTTOM: 61.82,19.15 61.82,19.81 61.24,20.4 51.99,20.4 51.23,19.63 51.23,19.1 51.82,18.52 52.53,18.52 53.11,19.1 61.77,19.1
N12358168 on BOTTOM: 29.79,32.61 29.79,36.25 29.77,36.25 28.02,34.49 28.02,34.39
N12358168 on BOTTOM: 9.83,60.93 9.83,55.68 14.05,51.46 14.11,51.52 18.22,51.52 18.31,51.61 18.31,51.84 16.76,53.39 16.76,57.86 17.45,58.55 17.45,59.92 16.43,60.93
N12358168 on BOTTOM: 18.24,62.03 18.85,61.42 18.26,60.83 18.85,60.25 18.24,59.64 18.85,59.03 18.26,58.45 10.49,58.44 9.87,59.07 9.87,61.12 10.77,62.03
N12358168 on BOTTOM: 29.82,33.12 29.82,30.43 29.21,29.82 28.63,30.4 28.04,29.82 27.43,30.43 26.82,29.82 26.24,30.4 26.24,34.82 26.64,35.23 27.71,35.23
N12370171 on BOTTOM: 48.92,132.08 55.27,132.08 51.46,128.27 51.46,123.19 50.83,122.56 48.92,122.56 38.13,111.76 33.68,111.76 32.99,112.45 32.99,116.15
N12370179 on BOTTOM: 56.44,119.56 57.43,118.57 57.43,116.59 56.34,115.49 52.86,115.49 50.5,117.86 50.5,119.1 50.95,119.56
N12370503 on BOTTOM: 61.57,107.95 61.57,109.27 61.26,109.58 52.12,109.58 52.11,109.56 51.5,109.56 51.05,109.12 51.05,107.47 51.44,107.09 52.7,107.09 53.57,107.95
N12370525 on BOTTOM: 74.4,108.2 74.4,111.25 74.3,111.35 73.13,111.35 72.92,111.15 72.92,108.23 72.95,108.2
N12370663 on BOTTOM: 72.95,106.65 74.52,106.65 75.08,107.21 76.53,107.21 76.53,106.4 76.48,106.35 72.95,106.35
N12410952 on BOTTOM: 55.78,114.6 56.36,114.02 56.36,112.39 56.35,112.39 55.82,111.87 55.82,111.87 52.76,111.87 51.8,110.92 48.62,110.92 47.68,111.86 47.68,113.44 48.84,114.6

Small or netless copper shapes (teardrops, artwork), in the pictures only: 2 on BOTTOM

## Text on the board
Ref Des/Silkscreen Bottom: N | L
Ref Des/Silkscreen Top: 2245 | DER-977 | REV C | S/N | HS1 | SG | N | L
TOLERANCE_BOTTOM: 14.  FAB HOUSE LOGO,DATE CODE TO BE IN SILK SCREEN ONLY.DO NOT USE COPPER. | 13.  MATERIAL DOUBLE SIDED (TOP & BOTTTOM) FR4 COPPER 2oz THICKNESS 0.062" | PLEASE DELETE THESE PINS(IF ANY) | Please note one (1) slot here.
User.9: FIGURE | FINISHED_SIZE | 0.4572 | 0.508 | 0.75 | 0.762 | 0.889 | 0.9652 | 1.016 | 1.27 | 1.4986 | 1.524 | 1.7018 | 2.032 | 2.794 | 3.9624 | DRILL CHART: TOP to BOTTOM | ALL UNITS ARE IN MILLIMETERS | TOLERANCE_DRILL | +0.0762/-0.0762 | +0.0/-0.0 | PLATED | QTY | 12 | 191 | 1 | 6 | 4 | 3 | 8 | 20 | 2 | 9 | 293 | TOTAL HOLES:
